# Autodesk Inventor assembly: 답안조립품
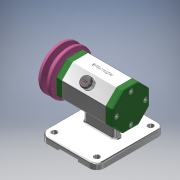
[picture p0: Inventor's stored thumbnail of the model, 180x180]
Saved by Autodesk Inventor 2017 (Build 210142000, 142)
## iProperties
Part Number: 답안조립품
Material: 일반
Document SubType Name: Assembly
Designer: Administrator
Author: Administrator
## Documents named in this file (16)
- C:\Users\Administrator\Desktop\721006V1005\답안조립품.iam
- C:\Users\Administrator\Desktop\721006V1005\본체.ipt
- C:\Users\Administrator\Desktop\721006V1005\베어링 6002.ipt
- C:\Users\Administrator\Desktop\721006V1005\뒤커버.ipt
- C:\Users\Administrator\Desktop\721006V1005\앞커버.ipt
- C:\Users\Administrator\Desktop\721006V1005\오일 실 15x25x7.ipt
- C:\Users\Administrator\Desktop\721006V1005\볼트 M4x12.ipt
- C:\Users\Administrator\Desktop\721006V1005\축.ipt
- C:\Users\Administrator\Desktop\721006V1005\키 3x3x12.ipt
- 키 3x3x12.ipt
- C:\Users\Administrator\Desktop\721006V1005\V벨트풀리.ipt
- C:\Users\Administrator\Desktop\721006V1005\와셔 8x17.ipt
- C:\Users\Administrator\Desktop\721006V1005\스프링와셔 8.ipt
- C:\Users\Administrator\Desktop\721006V1005\너트 M8.ipt
- 너트 M8.ipt
- C:\Users\Administrator\Desktop\721006V1005\고무캡.ipt
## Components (2 placed, 2 different names)
1. V벨트풀리:1
2. 고무캡:1
